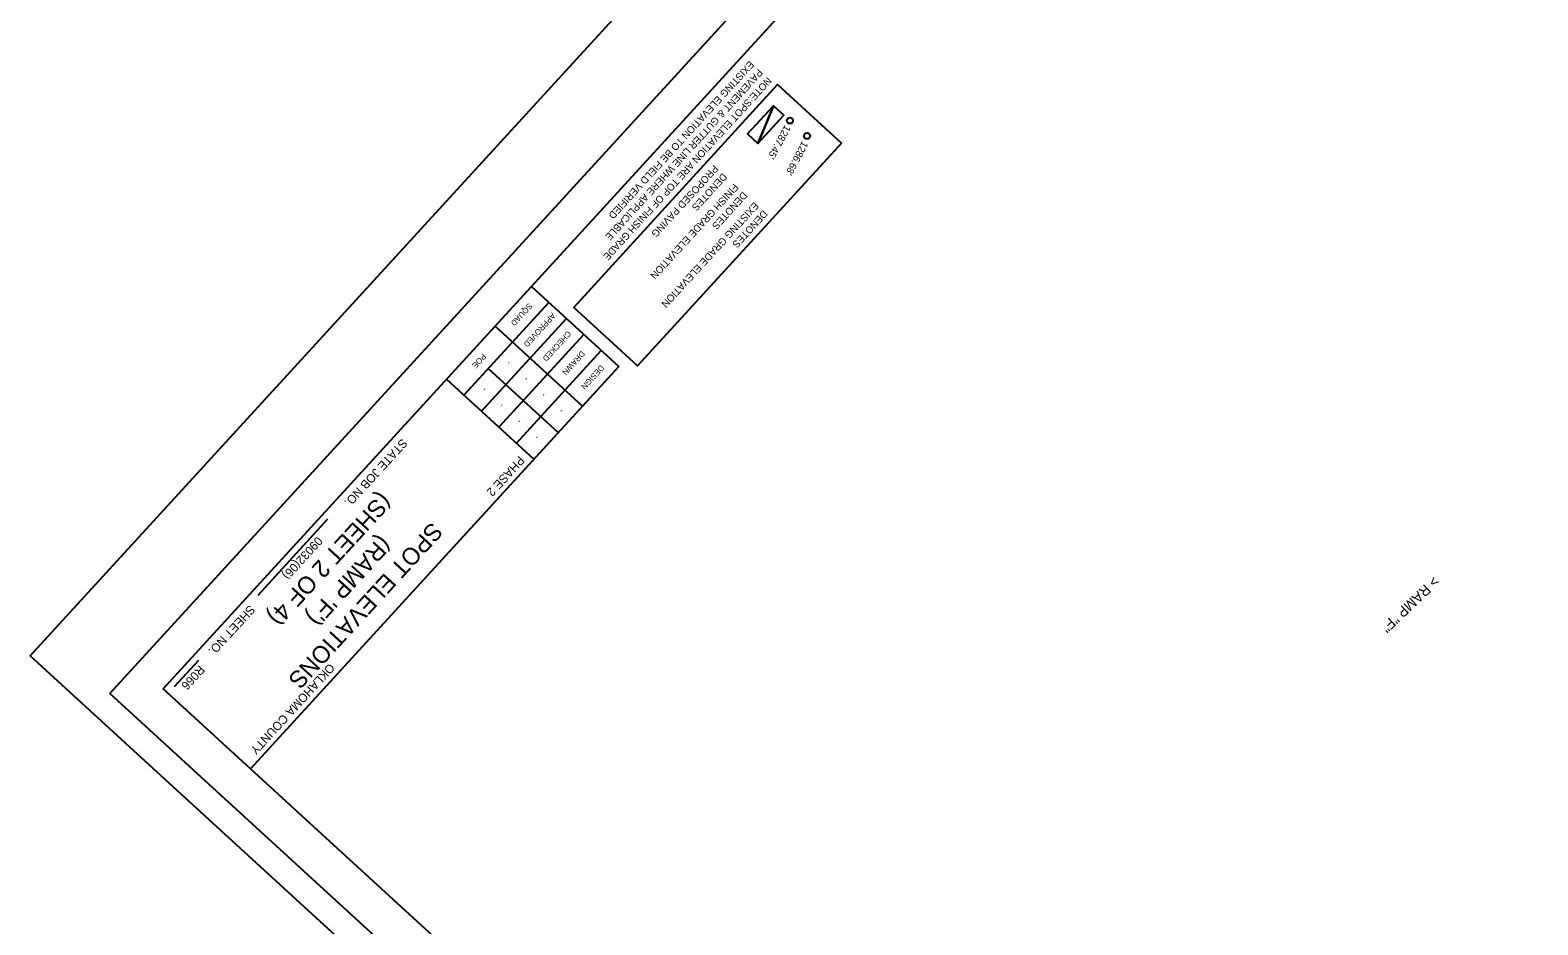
# Model space of a CAD drawing. Extents: x 2149762 to 2151023, y 143269 to 144552.
# Drawn here: x 2149762 to 2150393, y 143643 to 144017 of the extents above; entities that cross this region are included whole.
import ezdxf

# ---------------------------------------------------------------- set-up
doc = ezdxf.new("R2010")
doc.units = 0
for name, color, linetype in [('EX_Align_Text', 7, 'Continuous'), ('INR_Tracking', 7, 'Continuous'), ('PR_Align_Ramp_F_Label', 7, 'Continuous'), ('PR_Improvements_Txt', 7, 'Continuous'), ('PR_Misc_Improvement', 7, 'Continuous'), ('PR_Pattern_Area_Pavement_Phase_3', 7, 'Continuous'), ('PR_Shading_1', 7, 'Continuous'), ('SHT_Plot_Shape_Half', 7, 'Continuous'), ('SHT_Sheet_Border', 7, 'Continuous'), ('SHT_Standard_Sheet_Txt', 7, 'Continuous'), ('TOPO_Curb Gut', 7, 'Continuous'), ('TOPO_Fence', 7, 'Continuous'), ('TOPO_RR Rail', 7, 'Continuous')]:
    doc.layers.add(name, color=color, linetype=linetype)

msp = doc.modelspace()

# ---------------------------------------------------------------- linework, layer by layer
at = {"layer": 'PR_Improvements_Txt'}
for points in [[(2150101.57, 143969.56), (2150016.34, 143876.49), (2149989.71, 143900.87), (2150074.94, 143993.95)], [(2150077.51, 143981.21), (2150066.69, 143969.4), (2150062.4, 143973.33), (2150073.21, 143985.14)]]:
    msp.add_lwpolyline(points, close=True, dxfattribs=at)
at = {"layer": 'PR_Misc_Improvement'}
for centre in [(2150080.07, 143978.94), (2150087.23, 143972.53)]:
    msp.add_circle(centre, 1.27, dxfattribs=at)
at = {"layer": 'PR_Pattern_Area_Pavement_Phase_3'}
msp.add_line((2150073.21, 143985.14), (2150066.69, 143969.4), dxfattribs=at)
at = {"layer": 'PR_Shading_1'}
msp.add_lwpolyline([(2150073.21, 143985.14), (2150069.95, 143977.27), (2150066.69, 143969.4), (2150077.51, 143981.21), (2150073.21, 143985.14)], dxfattribs=at)
at = {"layer": 'SHT_Plot_Shape_Half'}
msp.add_lwpolyline([(2150971.44, 144046), (2150282.59, 143293.75), (2149795.84, 143739.47), (2150484.68, 144491.73)], close=True, dxfattribs=at)
at = {"layer": 'SHT_Sheet_Border'}
for p, q in [((2149972.02, 143909.66), (2150008.53, 143876.23)), ((2150008.53, 143876.23), (2149854.55, 143708.08)), ((2149936.57, 143870.94), (2149973.09, 143837.5))]:
    msp.add_line(p, q, dxfattribs=at)
msp.add_lwpolyline([(2149818.04, 143741.51), (2150456.24, 144438.45), (2150920.87, 144012.99), (2150282.67, 143316.05)], close=True, dxfattribs=at)
at = {"layer": 'TOPO_Curb Gut'}
msp.add_lwpolyline([(2151022.87, 144065.52), (2150293.5, 143269.01), (2149762.5, 143755.26), (2150491.86, 144551.76)], close=True, dxfattribs=at)
at = {"layer": 'TOPO_Fence'}
for p, q in [((2149956.83, 143893.07), (2149993.35, 143859.62)), ((2149954, 143875.32), (2149983.22, 143848.56)), ((2149886.81, 143812.34), (2149857.63, 143780.47)), ((2149832.82, 143753.38), (2149822.64, 143742.26))]:
    msp.add_line(p, q, dxfattribs=at)
for points in [[(2149943.87, 143864.26), (2149979.32, 143902.98)], [(2149951.17, 143857.57), (2149986.62, 143896.29)], [(2149958.47, 143850.89), (2149993.92, 143889.6)], [(2149965.77, 143844.2), (2150001.23, 143882.92)]]:
    msp.add_lwpolyline(points, dxfattribs=at)
at = {"layer": 'TOPO_RR Rail'}
msp.add_lwpolyline([(2150066.69, 143969.4), (2150069.95, 143977.27), (2150073.21, 143985.14), (2150062.4, 143973.33), (2150066.69, 143969.4)], dxfattribs=at)

# ---------------------------------------------------------------- texts
at = {"layer": 'EX_Align_Text'}
msp.add_text("1286.68' ", height=3, rotation=242.12677, dxfattribs=at).set_placement((2150085.24, 143970.55))
at = {"layer": 'INR_Tracking'}
msp.add_text("1287.45' ", height=3, rotation=241.32612, dxfattribs=at).set_placement((2150077.97, 143977.28))
at = {"layer": 'PR_Align_Ramp_F_Label'}
msp.add_text('> RAMP "F"', height=4.3, rotation=223.59345, dxfattribs=at).set_placement((2150349.01, 143788.87))
at = {"layer": 'PR_Improvements_Txt'}
for s, p in [('EXISTING ELEVATION TO BE FIELD VERIFIED', (2150063.16, 144004.13)), ('PAVEMENT & GUTTER LINE WHERE APPLICABLE', (2150066.85, 144000.74)), ('NOTE:SPOT ELEVATION ARE TOP OF FINISH GRADE', (2150070.55, 143997.36)), ('PROPOSED PAVING', (2150048.21, 143960.59)), ('DENOTES', (2150051.9, 143957.21)), ('FINISH GRADE ELEVATION', (2150056.67, 143952.85)), ('DENOTES', (2150060.36, 143949.46)), ('EXISTING GRADE ELEVATION', (2150065.13, 143945.1)), ('DENOTES', (2150068.82, 143941.72))]:
    msp.add_text(s, height=3, rotation=227.51948, dxfattribs=at).set_placement(p)
at = {"layer": 'SHT_Standard_Sheet_Txt'}
for s, height, p in [('SQUAD', 2.4, (2149970.91, 143902.89)), ('APPROVED', 2.4, (2149980.6, 143898.81)), ('CHECKED', 2.4, (2149987.1, 143891.26)), ('POE', 2.4, (2149951.59, 143881.79)), ('-', 2.4, (2149962.21, 143878.76)), ('DRAWN', 2.4, (2149992.88, 143882.91)), ('-', 2.4, (2149969.51, 143872.07)), ('DESIGN', 2.4, (2150000.91, 143877.02)), ('-', 2.4, (2149952.08, 143867.7)), ('-', 2.4, (2149959.38, 143861.01)), ('-', 2.4, (2149976.82, 143865.39)), ('-', 2.4, (2149966.69, 143854.32)), ('-', 2.4, (2149984.14, 143858.68)), ('-', 2.4, (2149974.01, 143847.62)), ('STATE JOB NO.', 3.6, (2149917.88, 143846.27)), ('PHASE 2', 3.621, (2149966.85, 143839.06)), ('(SHEET 2 OF 4)', 7.2, (2149909.01, 143823.98)), ('SPOT ELEVATIONS', 7.2, (2149930.27, 143811.59)), ('09032(06)', 3.6, (2149882.44, 143805.38)), ("(RAMP 'F')", 7.2, (2149908.85, 143806)), ('SHEET NO. ', 3.6, (2149854.2, 143776.72)), ('OKLAHOMA COUNTY', 3.6211, (2149887.52, 143752.43)), ('R066', 3.6, (2149833.18, 143751.58))]:
    msp.add_text(s, height=height, rotation=227.51948, dxfattribs=at).set_placement(p)

doc.saveas('drawing.dxf')
